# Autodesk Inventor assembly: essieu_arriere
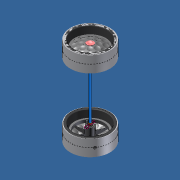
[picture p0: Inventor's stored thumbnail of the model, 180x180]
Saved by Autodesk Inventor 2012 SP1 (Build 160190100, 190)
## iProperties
Created: 2011-01
Part Number: essieu_arriere
Document SubType Name: Assembly
Designer: eric
Mass: 6204.37 g
Surface Area: 10780.2 cm^2
Volume: 6204.37 cm^3
Density: 1 g/cm^3
Author: eric
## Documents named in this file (5)
- D:\Cours\Inventor salle SI\chariot_de_golf_2008\chariot_de_golf_trolem\essieu_arriere.iam
- D:\Cours\Inventor salle SI\chariot_de_golf_2008\chariot_de_golf_trolem\62goupille_epingle_Defaut.ipt
- D:\Cours\Inventor salle SI\chariot_de_golf_2008\chariot_de_golf_trolem\montage7roue_caoutchouc_Defaut.iam
- D:\Cours\Inventor salle SI\chariot_de_golf_2008\chariot_de_golf_trolem\51axe_Defaut.ipt
- D:\Cours\Inventor salle SI\chariot_de_golf_2008\chariot_de_golf_trolem\12roue+axe_Defaut.iam
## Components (5 placed, 4 different names)
1. 12roue+axe_Defaut:1 [sub-assembly]
2. montage7roue_caoutchouc_Defaut:1 [sub-assembly]
3. montage7roue_caoutchouc_Defaut:2 [sub-assembly]
4. 51axe_Defaut:1
5. 62goupille_epingle_Defaut:1
